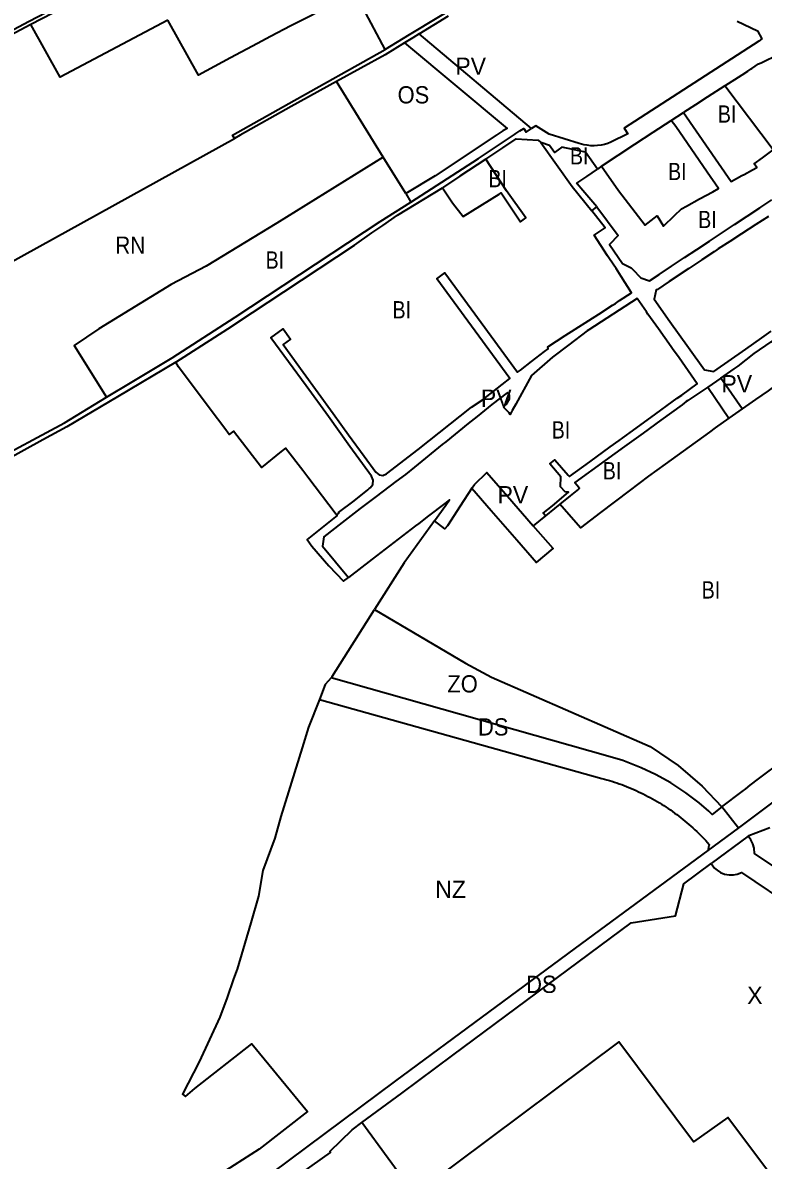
# Model space of a CAD drawing. Extents: x -650451 to -642268, y -1075216 to -1066610.
# Drawn here: x -648700 to -648056, y -1071706 to -1070717 of the extents above; entities that cross this region are included whole.
import ezdxf

# ---------------------------------------------------------------- set-up
doc = ezdxf.new("R2010")
doc.units = 0
doc.header["$LTSCALE"] = 6
doc.layers.add('1', color=7, linetype='Continuous', lineweight=35)
doc.layers.add('2', color=7, linetype='Continuous')
doc.layers.add('3', color=7, linetype='Continuous')

msp = doc.modelspace()

# ---------------------------------------------------------------- linework, layer by layer
at = {"layer": '1'}
for p, q in [((-648257.61, -1070808.91), (-648355.275, -1070726.455)), ((-648386.587, -1070833.807), (-648427.25, -1070767.95)), ((-648136.08, -1070801.79), (-648125.2, -1070794.79)), ((-648366.98, -1070865.44), (-648386.587, -1070833.807)), ((-648366.98, -1070865.44), (-648362.519, -1070872.788)), ((-648205.18, -1070880.5), (-648200.86, -1070877.05)), ((-648092.72, -1071025.89), (-648104.12, -1071033.78)), ((-648074.121, -1071052.749), (-648092.72, -1071025.89)), ((-648104.12, -1071033.78), (-648085.73, -1071060.92)), ((-648074.121, -1071052.749), (-648085.73, -1071060.92)), ((-648245.49, -1071145.91), (-648256.04, -1071154.5)), ((-648069.022, -1071424.443), (-648101.203, -1071448.31))]:
    msp.add_line(p, q, dxfattribs=at)
for points in [[(-648645.331, -1070689.546), (-648694.92, -1070715.85), (-648739.85, -1070739.54), (-648815.76, -1070782.92), (-648860.53, -1070807.99), (-648860.86, -1070807.36), (-648867.68, -1070797.55), (-648870.97, -1070789.43), (-648884.66, -1070755.61), (-648885.13, -1070741.96), (-648901.35, -1070694.37), (-648902.64, -1070691.87), (-648922.84, -1070635.69), (-648939.05, -1070590.62), (-648903.32, -1070575.91), (-648861.04, -1070556.21), (-648843.71, -1070548.13), (-648820.7, -1070537.41), (-648793.921, -1070526.057), (-648754.483, -1070509.232), (-648747.74, -1070506.7), (-648728.255, -1070500.709)], [(-648466.61, -1070600.21), (-648492.47, -1070614.2), (-648544.42, -1070639.42), (-648597.74, -1070668.62), (-648693.45, -1070718.46)], [(-648222.58, -1070643.48), (-648235.6, -1070651.17), (-648311.53, -1070695.29), (-648363.96, -1070727.29), (-648384.89, -1070740.06)], [(-648384.89, -1070740.06), (-648404.45, -1070703.55), (-648410.84, -1070690.42), (-648427.9, -1070699.29), (-648438.55, -1070704.83), (-648449.19, -1070710.37), (-648466.94, -1070719.6), (-648484.68, -1070728.83), (-648496.18, -1070734.81), (-648519.58, -1070747.4), (-648547.54, -1070762.44), (-648574.27, -1070714.5)], [(-648355.275, -1070726.455), (-648329.91, -1070710.86)], [(-648693.45, -1070718.46), (-648737.72, -1070741.88), (-648813.96, -1070785.53), (-648835.21, -1070797.94), (-648858.62, -1070811.62), (-648863.42, -1070813.31)], [(-648574.27, -1070714.5), (-648667.72, -1070764.15), (-648693.45, -1070718.46)], [(-648078.53, -1070715.55), (-648060.85, -1070723.82), (-648057.21, -1070730.8), (-648059.7, -1070732.7), (-648176.86, -1070808.52), (-648173.66, -1070813.37), (-648188.46, -1070820.7), (-648191.27, -1070821.79), (-648194.14, -1070822.65), (-648197.09, -1070823.28), (-648200.06, -1070823.68), (-648203.06, -1070823.84), (-648206.07, -1070823.76), (-648209.06, -1070823.44), (-648212.01, -1070822.89), (-648216.09, -1070821.99), (-648242.14, -1070813.82), (-648253.79, -1070806.34), (-648257.61, -1070808.91)], [(-648355.275, -1070726.455), (-648360.83, -1070729.87), (-648368.163, -1070734.376)], [(-648516.092, -1070817.462), (-648517.87, -1070814.68), (-648468.77, -1070787.09), (-648384.89, -1070740.06)], [(-648368.163, -1070734.376), (-648385.03, -1070744.74), (-648427.25, -1070767.95)], [(-648368.163, -1070734.376), (-648278.832, -1070808.761), (-648282.44, -1070810.84), (-648287.74, -1070814.32), (-648341.58, -1070849.98), (-648366.98, -1070865.44)], [(-648089.27, -1070771.57), (-648074.13, -1070762.04), (-648069.29, -1070758.81), (-648066.27, -1070756.8), (-648065.81, -1070756.49), (-648060.07, -1070752.67), (-648057.56, -1070751.63), (-648042.44, -1070744.09), (-648039.82, -1070742.33)], [(-648427.25, -1070767.95), (-648466.83, -1070789.54), (-648511.09, -1070814.7), (-648516.092, -1070817.462)], [(-648089.27, -1070771.57), (-648104.78, -1070781.65), (-648114.77, -1070788.08), (-648125.2, -1070794.79)], [(-648125.2, -1070794.79), (-648083.65, -1070854.89), (-648074.41, -1070849.79), (-648072.59, -1070848.79), (-648065.35, -1070844.8), (-648061.52, -1070842.68), (-648063.76, -1070839.49), (-648056.61, -1070834.26), (-648047.17, -1070827.35), (-648089.27, -1070771.57)], [(-648362.519, -1070872.788), (-648303.631, -1070834.849), (-648272.45, -1070814.075), (-648272.453, -1070814.072), (-648271.1, -1070813.17), (-648267.8, -1070810.96), (-648264.38, -1070808.66), (-648262.15, -1070811.96), (-648257.61, -1070808.91)], [(-648196.65, -1070841.7), (-648167.6, -1070822.53), (-648151.77, -1070812.11), (-648136.08, -1070801.79)], [(-648196.65, -1070841.7), (-648181.75, -1070862.74), (-648158.58, -1070892.98), (-648148.34, -1070884.92), (-648142.79, -1070893.78), (-648133.14, -1070884.6), (-648127, -1070878.75), (-648122.72, -1070876.44), (-648111.24, -1070870.11), (-648099.85, -1070863.82), (-648094.9, -1070861.09), (-648100, -1070853.35), (-648101.45, -1070851.34), (-648132.03, -1070807.05), (-648136.08, -1070801.79)], [(-648866.341, -1071000.881), (-648820.822, -1070978.778), (-648774.23, -1070956.42), (-648740.25, -1070941.21), (-648516.092, -1070817.462)], [(-648297.39, -1070835.36), (-648282.46, -1070825.6), (-648270.84, -1070817.79), (-648251.73, -1070819.07), (-648249.5, -1070821.08)], [(-648200.17, -1070844.094), (-648210.517, -1070829.445), (-648221.58, -1070827.03), (-648231.22, -1070824.92), (-648237.46, -1070829.68), (-648241.96, -1070823.46), (-648249.5, -1070821.08)], [(-648249.5, -1070821.08), (-648222.158, -1070859.221), (-648205.18, -1070880.5)], [(-648386.587, -1070833.807), (-648479.18, -1070891.26), (-648540.7, -1070928.6), (-648571.14, -1070944.67), (-648634.07, -1070983.17), (-648655.76, -1070997.5), (-648627.39, -1071042.65)], [(-648297.39, -1070835.36), (-648320.02, -1070850.16), (-648335.19, -1070860.49)], [(-648335.19, -1070860.49), (-648326.41, -1070873.55), (-648317.14, -1070885.48), (-648285.72, -1070865.96), (-648284.02, -1070864.91), (-648283.46, -1070865.74), (-648267.24, -1070889.9), (-648262.4, -1070886.58), (-648279.39, -1070862.98), (-648297.39, -1070835.36)], [(-648200.86, -1070877.05), (-648212.94, -1070862.74), (-648217.85, -1070856.93), (-648218.11, -1070856.44), (-648209.37, -1070850.44), (-648200.17, -1070844.094)], [(-648196.65, -1070841.7), (-648197.7, -1070842.39), (-648200.17, -1070844.094)], [(-648567.23, -1071012.14), (-648522.01, -1070983.2), (-648500.31, -1070968.88), (-648473.02, -1070951.04), (-648411.65, -1070910.37), (-648396.43, -1070899.48), (-648387.02, -1070893.13), (-648374.3, -1070884.27), (-648335.19, -1070860.49)], [(-648627.39, -1071042.65), (-648605.3, -1071029.34), (-648570.23, -1071008.2), (-648515.46, -1070972.94), (-648389.33, -1070889.79), (-648362.519, -1070872.788)], [(-648200.86, -1070877.05), (-648182.13, -1070901.91), (-648189.78, -1070909.77), (-648178.42, -1070926.29), (-648170.7, -1070930.1), (-648169.76, -1070931.2), (-648162.35, -1070938.7), (-648154.9, -1070941.2), (-648146.47, -1070935.75), (-648135.73, -1070928.6), (-648124.43, -1070921.16), (-648113.67, -1070914.01), (-648102.73, -1070906.8), (-648092.08, -1070899.75), (-648080.78, -1070892.32), (-648069.85, -1070885.16), (-648058.9, -1070877.9), (-648048.4, -1070870.83)], [(-648427.47, -1071144.54), (-648427.37, -1071144.46), (-648427.05, -1071144.84), (-648425.32, -1071143.41), (-648425.64, -1071143.03), (-648411.95, -1071132.74), (-648400.02, -1071123.14), (-648398.75, -1071122.13), (-648397.93, -1071121.43), (-648395.8, -1071118.4), (-648395.37, -1071114.71), (-648396.75, -1071111.27), (-648415.59, -1071085.36), (-648434.42, -1071059.47), (-648453.82, -1071032.79), (-648484.35, -1070990.83), (-648473.83, -1070983.18), (-648467.36, -1070992.07), (-648473.83, -1070996.78), (-648456.28, -1071020.91), (-648430.31, -1071056.63), (-648416.74, -1071075.28), (-648403.13, -1071093.99), (-648392.98, -1071107.94), (-648390.32, -1071110.08), (-648386.94, -1071110.57), (-648383.78, -1071109.28), (-648356.19, -1071088.13), (-648309.81, -1071051.22), (-648300.56, -1071045.19), (-648283.06, -1071031.47), (-648276.5, -1071026.27), (-648339.961, -1070939.551), (-648336.55, -1070937.07), (-648332.967, -1070934.458), (-648269.64, -1071020.93), (-648267.27, -1071019.12), (-648257.53, -1071011.38), (-648246.26, -1071002.78), (-648242.94, -1071000.36), (-648243.4, -1070998.72), (-648228.15, -1070988.97), (-648198.95, -1070970.32), (-648187.12, -1070962.62), (-648184.53, -1070960.94), (-648180.88, -1070958.56), (-648170.58, -1070951.86), (-648179.52, -1070937.49), (-648183.87, -1070930.66), (-648189.75, -1070922.11), (-648191.31, -1070919.65), (-648203.03, -1070901.58), (-648193.53, -1070895.09), (-648205.18, -1070880.5)], [(-648051.3, -1070885.22), (-648062.26, -1070892.34), (-648074.74, -1070900.43), (-648084.86, -1070907.08), (-648095.07, -1070913.6), (-648097.57, -1070915.26), (-648098.29, -1070915.73), (-648109.22, -1070922.99), (-648120.61, -1070930.56), (-648137.65, -1070941.89), (-648148.01, -1070948.77), (-648149.08, -1070949.3), (-648150.7, -1070957.43), (-648137.08, -1070976.62), (-648120.93, -1070999.44), (-648107.05, -1071018.89), (-648098.74, -1071020.34), (-648070.89, -1071000.73), (-648057.03, -1070990.99), (-648048.91, -1070985.24)], [(-648092.72, -1071025.89), (-648081.31, -1071017.99), (-648077.63, -1071015.44), (-648063.68, -1071004.56), (-648048.88, -1070994.33), (-648026.92, -1070979.95), (-648007.74, -1070966.29), (-647989.98, -1070953.85), (-647972.8, -1070941.37), (-647954.37, -1070928.31), (-647933.41, -1070913.4), (-647930.48, -1070913.2), (-647914.34, -1070939.36), (-647913.45, -1070940.79)], [(-647913.45, -1070940.79), (-647934.9, -1070955.87), (-647952.01, -1070967.82), (-647970.19, -1070980.45), (-647988.81, -1070993.27), (-648008.34, -1071006.32), (-648030.24, -1071021.91), (-648044.82, -1071032.25), (-648051.48, -1071036.97), (-648062.53, -1071044.59), (-648074.121, -1071052.749)], [(-648245.49, -1071145.91), (-648247.39, -1071143.59), (-648239.35, -1071137.05), (-648225.24, -1071125.33), (-648228.42, -1071124.8), (-648232.21, -1071120.62), (-648232.09, -1071111.97), (-648241.67, -1071100.55), (-648237.19, -1071096.94), (-648225.54, -1071110.33), (-648224.53, -1071111.5), (-648206.89, -1071098.72), (-648189.12, -1071085.85), (-648181.38, -1071080.25), (-648171.58, -1071073.15), (-648153.81, -1071060.27), (-648130.73, -1071043.55), (-648126.75, -1071040.67), (-648113.27, -1071030.91), (-648129.18, -1071008.42), (-648131.5, -1071005.16), (-648134.18, -1071001.42), (-648136.15, -1070998.65), (-648147.18, -1070983.19), (-648156.25, -1070970.2), (-648157.56, -1070968.32), (-648165.75, -1070956.59), (-648207.65, -1070983.91), (-648209.13, -1070984.88), (-648225.23, -1070997.14), (-648239.43, -1071007.83), (-648257.48, -1071023.77), (-648271.2, -1071048.64), (-648274.3, -1071054.25), (-648276.17, -1071057.66), (-648277.01, -1071056.12), (-648281.74, -1071051.41), (-648280.16, -1071048.51), (-648279.72, -1071048.93), (-648276.87, -1071044.12), (-648276.8, -1071041.07), (-648277.04, -1071040.13), (-648277.68, -1071039.32), (-648278.57, -1071038.86), (-648278.81, -1071038.85), (-648291.97, -1071048.8), (-648304.91, -1071059.26), (-648312.72, -1071065.57), (-648332.17, -1071081.28), (-648335.28, -1071083.79), (-648359.44, -1071103.31), (-648367.36, -1071109.7), (-648375.65, -1071115.96), (-648392.77, -1071128.9), (-648405.48, -1071138.49), (-648406.63, -1071139.36), (-648422.49, -1071151.66), (-648438.43, -1071164.01), (-648439.43, -1071172.29), (-648416.99, -1071199.46)], [(-648567.23, -1071012.14), (-648617.99, -1071042.21), (-648661.92, -1071068.24), (-648682.79, -1071079.69), (-648718.08, -1071099.04), (-648729.19, -1071105.13), (-648781.51, -1071132.24), (-648860.43, -1071173.14), (-648862.97, -1071168.09)], [(-648427.47, -1071144.54), (-648452.32, -1071112.08), (-648456.65, -1071106.41), (-648471.64, -1071086.81), (-648475.37, -1071089.83), (-648492.65, -1071103.8), (-648516.83, -1071072.11), (-648520.86, -1071075.05), (-648524.53, -1071069.93), (-648536.41, -1071054.13), (-648564.89, -1071016.27), (-648567.23, -1071012.14)], [(-648104.12, -1071033.78), (-648119, -1071043.73), (-648121.58, -1071045.46), (-648122.85, -1071046.42), (-648126.56, -1071049.2), (-648144.92, -1071062.5), (-648160.46, -1071073.78), (-648170.64, -1071081.18), (-648176.55, -1071085.47), (-648193.45, -1071097.76), (-648219.81, -1071116.92), (-648217.86, -1071119.2), (-648215.73, -1071121.72), (-648216.71, -1071122.51), (-648223.91, -1071128.37), (-648232.8, -1071135.6)], [(-648752.967, -1071111.861), (-648731.27, -1071100.77), (-648664.1, -1071064.78), (-648627.39, -1071042.65)], [(-648085.73, -1071060.92), (-648097.61, -1071069.37), (-648102.55, -1071072.86), (-648125.53, -1071089.51), (-648141.12, -1071100.71), (-648155.77, -1071111.23), (-648172.48, -1071123.95), (-648197.57, -1071143.03), (-648215.08, -1071156.35), (-648232.8, -1071135.6)], [(-648309.41, -1071121.655), (-648307.33, -1071118.47), (-648296.34, -1071108.04), (-648278.39, -1071128.74), (-648256.04, -1071154.5)], [(-648309.41, -1071121.655), (-648319.77, -1071137.52), (-648330.78, -1071154.36), (-648333.002, -1071157.07), (-648341.943, -1071150.071)], [(-648309.41, -1071121.655), (-648292.587, -1071141.054), (-648270.236, -1071166.815), (-648253.126, -1071186.542), (-648238.84, -1071174.33), (-648256.04, -1071154.5)], [(-648341.943, -1071150.071), (-648332.09, -1071136.43), (-648328.9, -1071132.02), (-648333.1, -1071135.21), (-648347.22, -1071145.94), (-648355.66, -1071152.35), (-648358.59, -1071154.57), (-648396.21, -1071183.48), (-648416.99, -1071199.46)], [(-648232.8, -1071135.6), (-648237.46, -1071139.38), (-648245.49, -1071145.91)], [(-648427.47, -1071144.54), (-648426.82, -1071145.4), (-648452.84, -1071166.32), (-648448.82, -1071172.06), (-648433.9, -1071189.43), (-648421.16, -1071202.66), (-648416.99, -1071199.46)], [(-648341.943, -1071150.071), (-648368.48, -1071186.81), (-648394.104, -1071227.17)], [(-648432.093, -1071286.645), (-648431.21, -1071285.62), (-648394.104, -1071227.17)], [(-648394.104, -1071227.17), (-648315.127, -1071274.052), (-648292.406, -1071286.112), (-648154.21, -1071346.477), (-648130, -1071363), (-648109, -1071381), (-648091.92, -1071399.07)], [(-648432.093, -1071286.645), (-648437.16, -1071292.53), (-648442.191, -1071305.453)], [(-648091.92, -1071399.07), (-648100.438, -1071405.517), (-648103.268, -1071402.88), (-648111.646, -1071395.618), (-648123.313, -1071386.696), (-648136.263, -1071378.194), (-648149.571, -1071370.788), (-648162.084, -1071364.918), (-648178.158, -1071358.781), (-648191.25, -1071354.858), (-648432.093, -1071286.645)], [(-648442.191, -1071305.453), (-648451.6, -1071329.62), (-648457.17, -1071347.52), (-648475.82, -1071407.52), (-648481.1, -1071426.24), (-648491.48, -1071454.4), (-648495.09, -1071476.72), (-648502, -1071500), (-648513.92, -1071540.24), (-648516.9, -1071548.64), (-648522.6, -1071564.73), (-648528.8, -1071582.1), (-648546.88, -1071620.72), (-648561.49, -1071648.91), (-648558.76, -1071650.94), (-648550.56, -1071644.12), (-648501.12, -1071605.06), (-648475.34, -1071636.18), (-648452.64, -1071663.99), (-648494.6, -1071696.95), (-648567.15, -1071743.16), (-648613.1, -1071768.02), (-648611.51, -1071771.2), (-648601.41, -1071789.09)], [(-648442.191, -1071305.453), (-648196.236, -1071374.226), (-648194.075, -1071374.813), (-648191.917, -1071375.427), (-648189.763, -1071376.067), (-648187.614, -1071376.733), (-648185.47, -1071377.426), (-648183.331, -1071378.146), (-648181.197, -1071378.891), (-648179.071, -1071379.664), (-648176.951, -1071380.462), (-648174.838, -1071381.286), (-648172.733, -1071382.137), (-648170.637, -1071383.013), (-648168.549, -1071383.915), (-648166.471, -1071384.843), (-648164.402, -1071385.797), (-648162.343, -1071386.776), (-648160.295, -1071387.78), (-648158.258, -1071388.809), (-648156.233, -1071389.864), (-648154.219, -1071390.942), (-648152.219, -1071392.046), (-648150.231, -1071393.173), (-648148.256, -1071394.325), (-648146.295, -1071395.5), (-648144.349, -1071396.699), (-648142.417, -1071397.922), (-648140.5, -1071399.167), (-648138.598, -1071400.435), (-648136.713, -1071401.725), (-648134.843, -1071403.038), (-648132.991, -1071404.373), (-648131.155, -1071405.729), (-648129.337, -1071407.106), (-648127.536, -1071408.504), (-648125.754, -1071409.922), (-648123.99, -1071411.361), (-648122.245, -1071412.82), (-648120.519, -1071414.298), (-648118.813, -1071415.795), (-648117.126, -1071417.311), (-648115.459, -1071418.845), (-648113.813, -1071420.397), (-648112.187, -1071421.967), (-648110.582, -1071423.554), (-648108.998, -1071425.156), (-648107.436, -1071426.776), (-648105.895, -1071428.411), (-648104.377, -1071430.062), (-648102.88, -1071431.729), (-648102.98, -1071432.031), (-648103.075, -1071432.336), (-648103.165, -1071432.642), (-648103.25, -1071432.951), (-648103.326, -1071433.244), (-648103.406, -1071433.571), (-648103.477, -1071433.883), (-648103.563, -1071434.301), (-648103.603, -1071434.511), (-648103.659, -1071434.826), (-648103.725, -1071435.248), (-648103.769, -1071435.565), (-648103.808, -1071435.882), (-648103.842, -1071436.2), (-648103.879, -1071436.624), (-648103.894, -1071436.837)], [(-648091.92, -1071399.07), (-648074.27, -1071385.62), (-648071.17, -1071383.26), (-648067.27, -1071380.27), (-648060.01, -1071374.69), (-648038.18, -1071358.51), (-648025.39, -1071348.76), (-648009.31, -1071336.48), (-647994.31, -1071325.03), (-647965.26, -1071302.86)], [(-648077.53, -1071417.4), (-648050.7, -1071397.66), (-648045.97, -1071393.99), (-648024.18, -1071377.18), (-648006.37, -1071365.15), (-647993.21, -1071357.57), (-647987.15, -1071354.07), (-647960.89, -1071343.84), (-647954.38, -1071342)], [(-648103.894, -1071436.837), (-648077.53, -1071417.4), (-648091.92, -1071399.07)], [(-648050.25, -1071417.19), (-648068.56, -1071424.1), (-648069.022, -1071424.443)], [(-648016.446, -1071471.268), (-648063.593, -1071439.723), (-648063.862, -1071435.078), (-648064.838, -1071431.28), (-648066.623, -1071427.592), (-648069.022, -1071424.443)], [(-648601.41, -1071789.09), (-648530.22, -1071749.16), (-648483.98, -1071717.99), (-648375.65, -1071637.42), (-648213.7, -1071517.79), (-648103.894, -1071436.837)], [(-648405.21, -1071673.54), (-648370.52, -1071648.07), (-648326.08, -1071615.1), (-648170.93, -1071500), (-648132.14, -1071493.74), (-648125, -1071465.96), (-648101.203, -1071448.31)], [(-648101.203, -1071448.31), (-648098.259, -1071452.196), (-648096.014, -1071454.192), (-648093.059, -1071456.066), (-648089.539, -1071457.489), (-648085.585, -1071458.248), (-648081.642, -1071458.215), (-648078.539, -1071457.636), (-648074.86, -1071456.248), (-648027.562, -1071487.894), (-648021.015, -1071492.264), (-647986.233, -1071514.148)], [(-647875.8, -1071654.22), (-647898.22, -1071694.24), (-647993.77, -1071766.7), (-648027.69, -1071748), (-648086.68, -1071669.2), (-648116.54, -1071690.46), (-648181.6, -1071603.39), (-648322.95, -1071708.86), (-648359.48, -1071736.12), (-648405.21, -1071673.54)], [(-648870.458, -1071929.441), (-648863.86, -1071928.28), (-648845.81, -1071923.07), (-648843.54, -1071922.41), (-648823.66, -1071915.5), (-648802.47, -1071904.83), (-648775.38, -1071891.36), (-648762.02, -1071884.71), (-648720.72, -1071863.86), (-648659.6, -1071833.2), (-648596.12, -1071802.62), (-648594.19, -1071801.61), (-648560.72, -1071784.13), (-648527.91, -1071765.32), (-648493.41, -1071743.02), (-648432.68, -1071699.61), (-648433.26, -1071698.81), (-648413.73, -1071680.02), (-648405.21, -1071673.54)]]:
    msp.add_lwpolyline(points, dxfattribs=at)

# ---------------------------------------------------------------- texts
at = {"layer": '2'}
for s, width, p in [('BI', 0.85, (-648112.501, -1070895.463)), ('BI', 0.85, (-648378.56, -1070974.021)), ('BI', 0.85, (-648239.972, -1071078.518)), ('BI', 0.85, (-648195.506, -1071114.091)), ('DS', 0.95, (-648262.237, -1071560.883))]:
    msp.add_text(s, height=15, dxfattribs=dict(at, width=width)).set_placement(p)
for s, p in [('PV', (-648301.693, -1071050.981)), ('NZ', (-648341.365, -1071478.233)), ('X', (-648069.871, -1071570.489))]:
    msp.add_text(s, height=15, dxfattribs=at).set_placement(p)
at = {"layer": '3'}
for p in [(-648323.889, -1070762.085), (-648092.298, -1071038.397), (-648287.201, -1071134.945)]:
    msp.add_text('PV', height=15, dxfattribs=at).set_placement(p)
for s, width, p in [('OS', 0.95, (-648374.128, -1070786.997)), ('BI', 0.85, (-648095.36, -1070803.704)), ('BI', 0.85, (-648224.144, -1070840.089)), ('BI', 0.85, (-648138.689, -1070853.699)), ('BI', 0.85, (-648295.064, -1070859.902)), ('RN', 0.9, (-648619.858, -1070917.825)), ('BI', 0.85, (-648489.027, -1070930.729)), ('BI', 0.85, (-648109.433, -1071217.739)), ('ZO', 0.95, (-648330.83, -1071299.485)), ('DS', 0.95, (-648304.141, -1071336.923))]:
    msp.add_text(s, height=15, dxfattribs=dict(at, width=width)).set_placement(p)

doc.saveas('drawing.dxf')
